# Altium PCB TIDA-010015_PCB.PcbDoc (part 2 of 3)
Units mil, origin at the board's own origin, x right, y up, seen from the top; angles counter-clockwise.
Board outline 6299.21 x 3149.61 mil, 2 copper layers (Top Layer, Bottom Layer), stack 64.6 mil thick; 232 components, 110 nets, 524 pads, 83 vias.
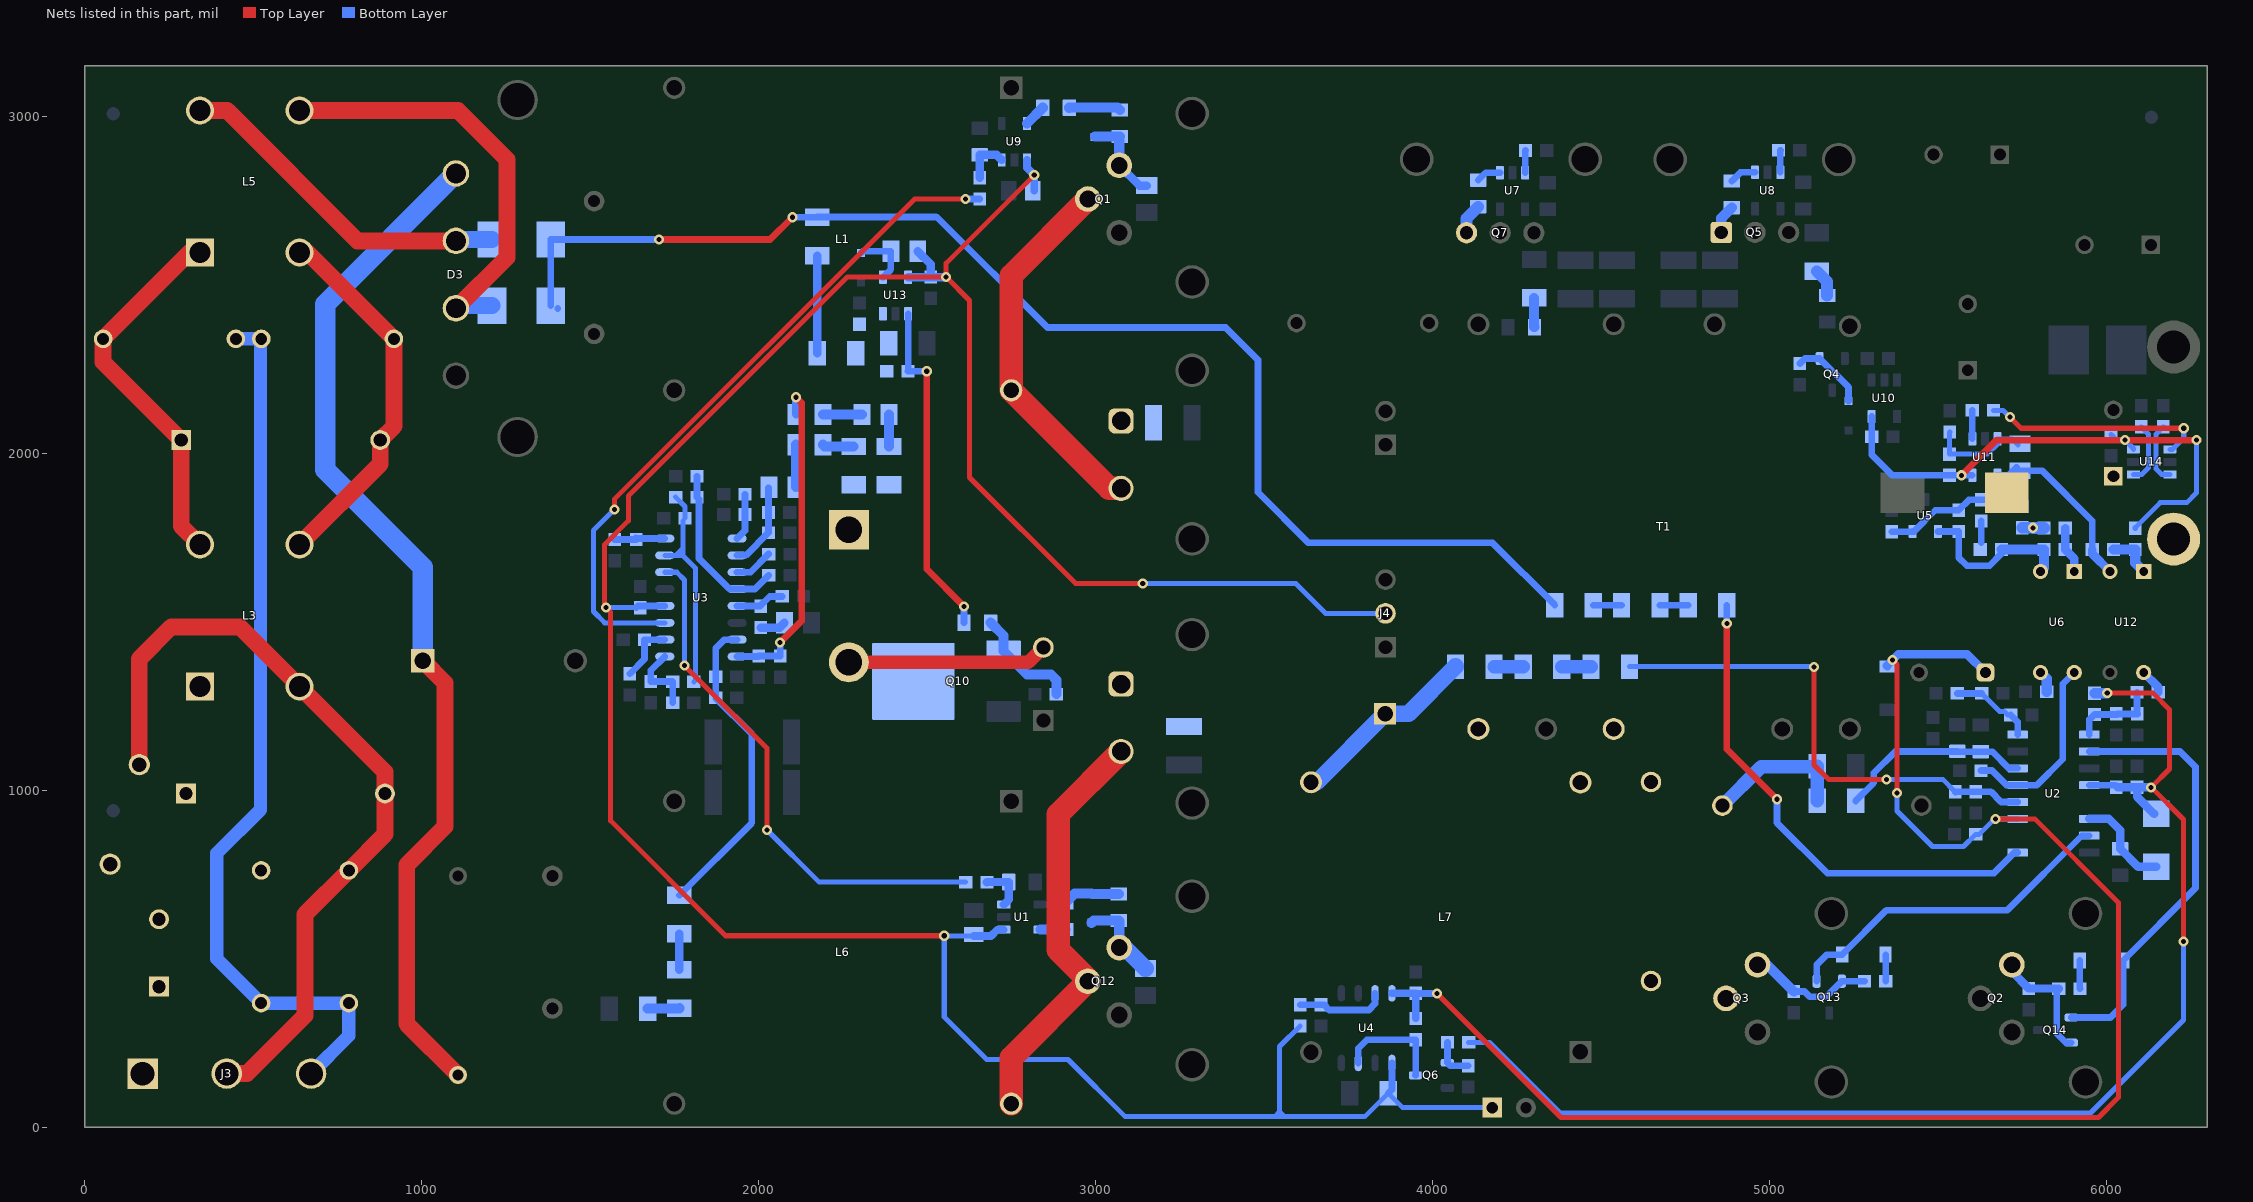
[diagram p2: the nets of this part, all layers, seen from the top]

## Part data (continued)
C34: "CAP, CERM, 820 pF, 50 V, +/- 5%, C0G/NP0, 0603", Cap_Case=0603, Manufacturer=AVX, Supplier Part Number 1=478-1186-1-ND, TempCo=C0G/NP0, Tolerance_%=5, Value1="0.052 ohm", Value2=50V, ValueDisplayed=820pF
C35: library part CMP-0007347-5, "CAP, CERM, 4.7 uF, 25 V, +/- 10%, X5R, 0603", Cap_Case=0603, Manufacturer=MuRata, Supplier Part Number 1=490-7203-1-ND, TempCo=X5R, Tolerance_%=10%, Value1=Unknown, Value2=25V, ValueDisplayed=4.7uF
C36: "CAP, CERM, 2.2 µF, 16 V, +/- 10%, X5R, 0805", Cap_Case=0805, Manufacturer=AVX, Supplier Part Number 1=478-2580-1-ND, TempCo=X5R, Tolerance_%=10, Value1="0.009 ohm", Value2=16V, ValueDisplayed=2.2µF
C38: library part CMP-0007445-4, "CAP, CERM, 0.22 uF, 50 V, +/- 10%, X7R, 0603", Cap_Case=0603, Manufacturer=MuRata, Supplier Part Number 1=490-12546-1-ND, TempCo=X7R, Tolerance_%=10%, Value1=Unknown, Value2=50V, ValueDisplayed=0.22uF
C39: "CAP, CERM, 150 pF, 1000 V, +/- 5%, U2J, 1206", Cap_Case=1206, Manufacturer=MuRata, Supplier Part Number 1=490-4302-1-ND, TempCo=U2J, Tolerance_%=5, Value1=Unknown, Value2=1000V, ValueDisplayed=150pF
C40: library part GRM31A7U3A151JW31D, "CAP CER 82PF 1KV U2J 1206", Cap_Case=1206, Manufacturer=MuRata, Supplier Part Number 1=490-8332-1-ND, TempCo=U2J, Tolerance_%=5, Value1=Unknown, Value2=1000V, ValueDisplayed=82pF
C41: "CAP, CERM, 1000 pF, 100 V, +/- 20%, X7R, 0603", Cap_Case=0603, Manufacturer=AVX, Supplier Part Number 1=478-3699-1-ND, TempCo=X7R, Tolerance_%=20, Value1="0.276 ohm", Value2=100V, ValueDisplayed=1000pF
C42: library part CMP-0006757-5, "CAP, CERM, 0.047 uF, 25 V, +/- 5%, X7R, 0603", Cap_Case=0603, Manufacturer=AVX, Supplier Part Number 1=478-3716-1-ND, TempCo=X7R, Tolerance_%=5%, Value1="0.052 ohm", Value2=25V, ValueDisplayed=0.047uF
C43: "CAP, CERM, 680 pF, 50 V, +/- 10%, X7R, 0603", Cap_Case=0603, Manufacturer=MuRata, Supplier Part Number 1=490-1491-1-ND, TempCo=X7R, Tolerance_%=10, Value1=Unknown, Value2=50V, ValueDisplayed=680pF
C44 C45: library part CMP-0008475-2, "CAP, CERM, 330 pF, 100 V, +/- 5%, C0G/NP0, 1206", Cap_Case=1206, Manufacturer=AVX, Supplier Part Number 1=478-1447-1-ND, TempCo=C0G/NP0, Tolerance_%=5%, Value1="0.392 ohm", Value2=100V, ValueDisplayed=330pF
C46 C48: "CAP, CERM, 1 µF, 25 V, +/- 10%, X7R, 0805", Cap_Case=0805, Manufacturer=Kemet, Supplier Part Number 1=399-8004-1-ND, TempCo=X7R, Tolerance_%=10, Value1=Unknown, Value2=25V, ValueDisplayed=1µF
C50: "CAP, CERM, 10 pF, 50 V,+/- 5%, C0G/NP0, 0603", Cap_Case=0603, Manufacturer=AVX, Supplier Part Number 1=478-1163-1-ND, TempCo=C0G/NP0, Tolerance_%=5, Value1="0.403 ohm", Value2=50V, ValueDisplayed=10pF
C51: "CAP, CERM, 1uF, 25V, +/-10%, X5R, 1206", Cap_Case=1206, Manufacturer=MuRata, Supplier Part Number 1=490-1807-1-ND, TempCo=X5R, Tolerance_%=10, Value1="0.01 ohm", Value2=25V, ValueDisplayed=1uF
C53 C54: library part CMP-0007356-5, "CAP, CERM, 2.2 uF, 35 V, +/- 10%, X5R, 0603", Cap_Case=0603, Manufacturer=MuRata, Supplier Part Number 1=490-7204-6-ND, TempCo=X5R, Tolerance_%=10%, Value1=Unknown, Value2=35V, ValueDisplayed=2.2uF
C55 C57: library part CMP-0007006-5, "CAP, CERM, 1 uF, 25 V, +/- 10%, X5R, 0603", Cap_Case=0603, Manufacturer=TDK, Supplier Part Number 1=445-5146-1-ND, TempCo=X5R, Tolerance_%=10%, Value1=Unknown, Value2=25V, ValueDisplayed=1uF
C56: library part CMP-0081052-1, "CAP, CERM, 4.7 µF, 16 V,+/- 10%, X5R, AEC-Q200 Grade 3, 0603", Cap_Case=0603, Manufacturer=MuRata, Supplier Part Number 1=490-12319-1-ND, TempCo=X5R, Tolerance_%=10%, Value2=16V, ValueDisplayed=4.7µF
C58 C59: "CAP, CERM, 100 pF, 50 V,+/- 5%, C0G/NP0, 0805", Cap_Case=0805, Manufacturer=AVX, Supplier Part Number 1=478-1316-1-ND, TempCo=C0G/NP0, Tolerance_%=5, Value1="0.356 ohm", Value2=50V, ValueDisplayed=100pF
C60: library part CMP-0064896-2, "1000µF 35V Aluminum Electrolytic Capacitors Radial, Can 10000 Hrs @ 105°C", Cap_Case=10x12.5, Manufacturer=Panasonic, Supplier Part Number 1=P10323-ND, Tolerance_%=20%, Value2=35V, ValueDisplayed=1000µF
C67 C68 C72 C73: "CAP, CERM, 4.7 µF, 100 V, +/- 10%, X7S, 1210", Cap_Case=1210, Manufacturer=TDK, Supplier Part Number 1=445-8912-1-ND, TempCo=X7S, Tolerance_%=10, Value1=Unknown, Value2=100V, ValueDisplayed=4.7µF
D1 D5: library part CMP-0029037-1, "Diode, Ultrafast, 600 V, 8 A, TH", Manufacturer="ON Semiconductor", Supplier Part Number 1=MUR860GOS-ND, Value1=8A, Value2=0.98V
D2 D6: "Diode, Schottky, 30V, 0.2A, SOD-323", Manufacturer="ON Semiconductor", Supplier Part Number 1=BAT54HT1OSCT-ND, Value1=0.2A, Value2=30V
D3: library part GBU4A-BP, "RECT BRIDGE GPP 1000V 25A GBU", Manufacturer="Comchip Technology", Value1=8A, Value2=50V
D4: library part CMP-0005844-2, "Diode, Zener, 15 V, 300 mW, SOD-323", Manufacturer="NXP Semiconductor", Power_W=300mW, Supplier Part Number 1=568-6280-1-ND, Value1=0.3W
D7 D8 D11: "Diode, Schottky, 30 V, 0.35 A, SOD-123", Manufacturer="Diodes Inc.", Supplier Part Number 1=SD103-BWDICT-ND, Value1=0.35A, Value2=0.55V
D9 D10: "Diode, P-N, 1000 V, 1 A, SMB", Manufacturer="Diodes Inc.", Supplier Part Number 1=RS1MB-FDICT-ND, Value1=1A, Value2=1.3V
D18: "Diode, Ultrafast, 600 V, 1 A, SMA", Manufacturer="Diodes Inc.", Supplier Part Number 1=US1J-FDICT-ND, Value1=1A, Value2=1.7V
D20: library part CMP-0005865-1, "Diode, Zener, 5.1 V, 200 mW, SOD-323", Manufacturer="Diodes Inc.", Power_W=200mW, Supplier Part Number 1=BZT52C5V1S-FDICT-ND, Value1=0.2W
F1: "FUSE, BOARD MOUNT, 10 A, 300 V, TH-2P", Manufacturer="LITTELFUSE INC"
FID1 FID2 FID3: "Fiducial mark.  There is nothing to buy or mount.", Manufacturer=N/A
H1 H2 H3 H4 H5 H6: "Bumpon, Hemisphere, 0.44 X 0.20, Clear", Manufacturer=3M, Supplier Part Number 1=SJ5303-7-ND
H7: library part CMP-0004065-1, "HEATSINK, ALUM, ANOD, for TO-220", Manufacturer="Assman WSW", Supplier Part Number 1=AE10901-ND
J1: library part CMP-0054792-1, "Header, 2.54 mm, 1x1, Gold, TH", Manufacturer="Wurth Elektronik", Supplier Part Number 1=732-5314-ND
J2: library part CMP-0055085-1, "Header, 100mil, 2x1, TH", Manufacturer=Mill-Max, Supplier Part Number 1=ED7202-ND
J3: "Header(Shrouded), 6.35mm, 3x1, Tin, TH", Manufacturer="TE Connectivity", Supplier Part Number 1=A1468-ND
J4: library part CMP-0055332-1, "Header, 2.54mm, 3x1, Tin, TH", Color=Black, Current_A=4A, Manufacturer=Molex, Supplier Part Number 1=WM50016-03-ND, Voltage_V=250V
J5: library part CMP-0055333-1, "Header, 2.54mm, 2x1, Tin, TH", Color=Black, Current_A=4A, Manufacturer=Molex, Supplier Part Number 1=WM50016-02-ND, Voltage_V=250V
L1 L6: library part PFC4124QM-161K06D-00, "Transformer, 160 uH, TH"
L2: library part 7447020, "Inductor, Toroid, Powdered Iron, 150 µH, 5A, TH", Manufacturer="Wurth Elektronik", Supplier Part Number 1=732-1427-ND, Value1="0.16 ohm", Value2=5A, ValueDisplayed=150µH
L3 L5: "FILTER, WE-CMBNC COMMON MODE POWER LINE CHOKE, 1mH, 15A, VERTICAL, TH-4P", Manufacturer="Wurth Elektronics"
L4: library part CMP-0062077-1, "Inductor, Ferrite, 300 nH, 32 A, 0.00031 ohm, SMD", Manufacturer="Pulse Engineering", Supplier Part Number 1=553-2161-1-ND, Value1="0.00031 ohm", Value2=32A, ValueDisplayed=300nH
L7: library part 1140-331K-RC, "Inductor, Ferrite, 330 µH, 6.1 A, 0.074 ohm, TH"
Logo1: library part Pb-Free
Logo2: library part ESD_Susceptible, "ESD Susceptible Symbol"
LOGO3 LOGO9: library part IEC_HotSurface, "IEC 61010-1 Hot Surface Warning"
LOGO4 LOGO7 LOGO8 LOGO10: library part IEC_HighVoltage, "IEC 61010-1 High Voltage Warning"
Logo6: library part FCC_disclaimer, "FCC_disclaimer"
M1 M2 M3 M4 M5 M6 M7 M8: "HEATSINK, ALUMINIUM WITH CLIP, VERTICAL MOUNT, SOLDERABLE PIN, TO-220", Manufacturer=OHMITE
Q1 Q2 Q3 Q12: library part CMP-0001223-3, "MOSFET N-CHANNEL 600V 26A TO220", Alternate Manufacturer=None, Manufacturer="Infineon Technologies", PartNumber=IPA60R120P7XKSA1, Supplier Part Number 1=IPA60R120P7XKSA1-ND, Value2="37 nC"
Q4: library part CMP-0000488-2, "Transistor, NPN, 60 V, 0.5 A, AEC-Q101, SOT-23", Manufacturer="ON Semiconductor", Supplier Part Number 1=MMBTA05LT1GOSCT-ND, Value1="0.5 A"
Q5 Q7: library part CMP-0000914-1, "MOSFET, N-CH, 80 V, 100 A, KCS0003B (TO-220-3)", Alternate Manufacturer=None, Manufacturer="Texas Instruments", Supplier Part Number 1=296-37286-5-ND, Value2="38 nC"
Q6: library part CMP-0000421-2, "Transistor, NPN, 30 V, 0.6 A, SOT-23", Manufacturer="ON Semiconductor", Supplier Part Number 1=MMBT2222LT1GOSCT-ND, Value1="0.6 A", Value2=300
Q10: library part CMP-0001138-3, "MOSFET, N-CH, 600 V, 4 A, DPAK", Alternate Manufacturer=None, Manufacturer=AOS, Supplier Part Number 1=785-1265-1-ND, Value2="6 nC"
Q13 Q14: library part "BC858C-7-F, Diodes Inc.", "Transistor, PNP, 30 V, 0.1 A, SOT-23", Manufacturer="Diodes Inc.", Supplier Part Number 1=BC858C-7-F-ND, Value1="0.1 A", Value2=600
R1 R2 R55 R64 R72: "RES, 10 k, 0.01%, 0.063 W, 0603", Manufacturer="Stackpole Electronics Inc", Power_W=0.063, Supplier Part Number 1=RNCF0603TKY10K0CT-ND, TempCo="5 ppm/C", Tolerance_%=0.01, Value1=0.01%, Value2=0.063W, Value_Code=10k0, ValueDisplayed=10k
R3: library part CMP-0018911-2, "RES, 200, 0.1%, 0.125 W, 0805", Manufacturer="Susumu Co Ltd", Power_W=125mW, Supplier Part Number 1=RG20P200BCT-ND, TempCo="25 ppm/C", Tolerance_%=0.1%, Value2=0.125W, Value_Code=200R, ValueDisplayed=200
R4 R5 R18: "RES, 18.2, 1%, 0.125 W, 0805", Manufacturer=Vishay-Dale, Power_W=0.125, Supplier Part Number 1=541-18.2CCT-ND, TempCo="100 ppm/C", Tolerance_%=1, Value1=1%, Value2=0.125W, Value_Code=18R2, ValueDisplayed=18.2
R6 R19 R74: "RES, 10.0 k, 1%, 0.125 W, 0805", Manufacturer=Vishay-Dale, Power_W=0.125, Supplier Part Number 1=541-10.0KCCT-ND, TempCo="100 ppm/C", Tolerance_%=1, Value1=1%, Value2=0.125W, Value_Code=10k0, ValueDisplayed=10.0k
R7 R8: "RES, 0.03, 1%, 2 W, 2512", Manufacturer="Stackpole Electronics Inc", Power_W=2, Supplier Part Number 1=CSRN2512FK30L0CT-ND, TempCo="200 ppm/C", Tolerance_%=1, Value1=1%, Value2=2W, Value_Code=R030, ValueDisplayed=0.03
R9: library part CMP-0024361-3, "RES, 59.7 k, 0.1%, 0.1 W, 0603", Manufacturer="Yageo America", Power_W=100mW, TempCo="25 ppm/C", Tolerance_%=0.1%, Value2=0.1W, Value_Code=59k7, ValueDisplayed=59.7k
R10 R22 R31: "RES, 1.00 k, 1%, 0.25 W, 1206", Manufacturer=Vishay-Dale, Power_W=0.25, Supplier Part Number 1=541-1.00KFCT-ND, TempCo="100 ppm/C", Tolerance_%=1, Value1=1%, Value2=0.25W, Value_Code=1k00, ValueDisplayed=1.00k
R11 R37 R39 R41: "RES, 66.5 k, 1%, 0.1 W, 0603", Manufacturer=Vishay-Dale, Power_W=0.1, Supplier Part Number 1=541-66.5KHCT-ND, TempCo="100 ppm/C", Tolerance_%=1, Value1=1%, Value2=0.1W, Value_Code=66k5, ValueDisplayed=66.5k
R12 R49: "RES, 10.0 k, 1%, 0.1 W, 0603", Manufacturer=Vishay-Dale, Power_W=0.1, Supplier Part Number 1=541-10.0KHCT-ND, TempCo="100 ppm/C", Tolerance_%=1, Value1=1%, Value2=0.1W, Value_Code=10k0, ValueDisplayed=10.0k
R14: library part CMP-0022705-3, "RES, 49.9 k, 1%, 0.1 W, AEC-Q200 Grade 0, 0603", Manufacturer=Panasonic, Power_W=100mW, Supplier Part Number 1=P49.9KHCT-ND, TempCo="100 ppm/C", Tolerance_%=1%, Value2=0.1W, Value_Code=49k9, ValueDisplayed=49.9k
R15 R16: "RES, 2.2, 5%, 0.125 W, 0805", Manufacturer=Vishay-Dale, Power_W=0.125, Supplier Part Number 1=541-2.2ACT-ND, TempCo="200 ppm/C", Tolerance_%=5, Value1=5%, Value2=0.125W, Value_Code=2R20, ValueDisplayed=2.2
R17 R47 R71 R73: "RES, 6.04 k, 1%, 0.1 W, 0603", Manufacturer=Vishay-Dale, Power_W=0.1, Supplier Part Number 1=541-6.04KHCT-ND, TempCo="100 ppm/C", Tolerance_%=1, Value1=1%, Value2=0.1W, Value_Code=6k04, ValueDisplayed=6.04k
R20: library part CMP-0018672-3, "RES, 3.0 M, 5%, 0.25 W, AEC-Q200 Grade 0, 1206", Manufacturer=Vishay-Dale, Power_W=250mW, Supplier Part Number 1=541-3.0MECT-ND, TempCo="200 ppm/C", Tolerance_%=5%, Value2=0.25W, Value_Code=3M00, ValueDisplayed=3.0M
R21 R23 R33 R87: library part CMP-0018647-3, "RES, 2.7 M, 5%, 0.25 W, AEC-Q200 Grade 0, 1206", Manufacturer=Vishay-Dale, Power_W=250mW, Supplier Part Number 1=541-2.7MECT-ND, TempCo="200 ppm/C", Tolerance_%=5%, Value2=0.25W, Value_Code=2M70, ValueDisplayed=2.7M
R24 R26: "RES, 16.5 k, 1%, 0.1 W, 0603", Manufacturer=Vishay-Dale, Power_W=0.1, Supplier Part Number 1=541-16.5KHCT-ND, TempCo="100 ppm/C", Tolerance_%=1, Value1=1%, Value2=0.1W, Value_Code=16k5, ValueDisplayed=16.5k
R25: "RES, 750 k, 1%, 0.1 W, 0603", Manufacturer=Vishay-Dale, Power_W=0.1, Supplier Part Number 1=541-750KHCT-ND, TempCo="100 ppm/C", Tolerance_%=1, Value1=1%, Value2=0.1W, Value_Code=750k
R27 R34 R46 R86: "RES, 2.74 M, 1%, 0.125 W, 0805", Manufacturer=Vishay-Dale, Power_W=0.125, Supplier Part Number 1=541-2.74MCCT-ND, TempCo="100 ppm/C", Tolerance_%=1, Value1=1%, Value2=0.125W, Value_Code=2M74, ValueDisplayed=2.74M
R28 R77: "RES, 511k ohm, 1%, 0.25W, 1206", Manufacturer=Vishay-Dale, Power_W=0.25, Supplier Part Number 1=541-511KFCT-ND, TempCo="100 ppm/C", Tolerance_%=1, Value1=1%, Value2=0.25W, Value_Code=511k
R29 R36: "RES, 330 k, 5%, 0.25 W, 1206", Manufacturer=Vishay-Dale, Power_W=0.25, Supplier Part Number 1=541-330KECT-ND, TempCo="200 ppm/C", Tolerance_%=5, Value1=5%, Value2=0.25W, Value_Code=330k
R30: "RES, 100, 1%, 0.1 W, 0603", Manufacturer=Vishay-Dale, Power_W=0.1, Supplier Part Number 1=541-100HCT-ND, TempCo="100 ppm/C", Tolerance_%=1, Value1=1%, Value2=0.1W, Value_Code=100R, ValueDisplayed=100
R32 R70: "RES, 487 k, 1%, 0.1 W, 0603", Manufacturer=Vishay-Dale, Power_W=0.1, Supplier Part Number 1=541-487KHCT-ND, TempCo="100 ppm/C", Tolerance_%=1, Value1=1%, Value2=0.1W, Value_Code=487k
R35: "RES, 133 k, 1%, 0.1 W, 0603", Manufacturer=Vishay-Dale, Power_W=0.1, Supplier Part Number 1=541-133KHCT-ND, TempCo="100 ppm/C", Tolerance_%=1, Value1=1%, Value2=0.1W, Value_Code=133k
R38 R40: "RES, 22, 5%, 0.1 W, 0603", Manufacturer=Vishay-Dale, Power_W=0.1, Supplier Part Number 1=541-22GCT-ND, TempCo="200 ppm/C", Tolerance_%=5, Value1=5%, Value2=0.1W, Value_Code=22R0, ValueDisplayed=22
R42: "RES, 7.50 k, 1%, 0.1 W, 0603", Manufacturer=Vishay-Dale, Power_W=0.1, Supplier Part Number 1=541-7.50KHCT-ND, TempCo="100 ppm/C", Tolerance_%=1, Value1=1%, Value2=0.1W, Value_Code=7k50, ValueDisplayed=7.50k
R43: "RES, 374 k, 1%, 0.25 W, 1206", Manufacturer=Vishay-Dale, Power_W=0.25, Supplier Part Number 1=541-374KFCT-ND, TempCo="100 ppm/C", Tolerance_%=1, Value1=1%, Value2=0.25W, Value_Code=374k
R44 R45: "RES, 4.7 k, 5%, 0.1 W, 0603", Manufacturer=Bourns, Power_W=0.1, Supplier Part Number 1=CR0603-JW-472GLFCT-ND, TempCo="200 ppm/C", Tolerance_%=5, Value1=5%, Value2=0.1W, Value_Code=4k70, ValueDisplayed=4.7k
R48: "RES, 147 k, 1%, 0.1 W, 0603", Manufacturer=Vishay-Dale, Power_W=0.1, Supplier Part Number 1=541-147KHCT-ND, TempCo="100 ppm/C", Tolerance_%=1, Value1=1%, Value2=0.1W, Value_Code=147k
R50: "RES, 16.9 k, 1%, 0.1 W, 0603", Manufacturer=Vishay-Dale, Power_W=0.1, Supplier Part Number 1=541-16.9KHCT-ND, TempCo="100 ppm/C", Tolerance_%=1, Value1=1%, Value2=0.1W, Value_Code=16k9, ValueDisplayed=16.9k
R51 R63: library part CMP-0022010-4, "RES, 113 k, 1%, 0.1 W, AEC-Q200 Grade 0, 0603", Manufacturer=Vishay-Dale, Power_W=100mW, Supplier Part Number 1=541-113KHCT-ND, TempCo="100 ppm/C", Tolerance_%=1%, Value2=0.1W, Value_Code=113k
R52 R53: "RES, 10, 5%, 0.125 W, 0805", Manufacturer=Vishay-Dale, Power_W=0.125, Supplier Part Number 1=541-10ACT-ND, TempCo="200 ppm/C", Tolerance_%=5, Value1=5%, Value2=0.125W, Value_Code=10R0, ValueDisplayed=10
R56: library part CMP-0023630-3, "RES, 100 k, 0.1%, 0.1 W, 0603", Manufacturer="Yageo America", Power_W=100mW, Supplier Part Number 1=603-RT0603BRD07100KL, TempCo="25 ppm/C", Tolerance_%=0.1%, Value2=0.1W, Value_Code=100k
R58 R59: "RES, 10.0, 1%, 0.25 W, 0603", Manufacturer=Vishay-Dale, Power_W=0.25, Supplier Part Number 1=541-10.0SCT-ND, TempCo="100 ppm/C", Tolerance_%=1, Value1=1%, Value2=0.25W, Value_Code=10R0, ValueDisplayed=10.0
R60 R61: "RES, 4.7, 5%, 0.125 W, 0805", Manufacturer=Vishay-Dale, Power_W=0.125, Supplier Part Number 1=541-4.7ACT-ND, TempCo="200 ppm/C", Tolerance_%=5, Value1=5%, Value2=0.125W, Value_Code=4R70, ValueDisplayed=4.7
R62: library part CMP-0023252-5, "RES, 6.81 k, 1%, 0.1 W, 0603", Manufacturer=Yageo, Power_W=100mW, Supplier Part Number 1=311-6.81KHRCT-ND, TempCo="100 ppm/C", Tolerance_%=1%, Value2=0.1W, Value_Code=6k81, ValueDisplayed=6.81k
R65: library part CMP-0015849-2, "RES, 0.0005, 1%, 2 W, 2512", Manufacturer=Vishay-Dale, Power_W=2W, TempCo="400 ppm/C", Tolerance_%=1%, Value_Code=L5000, ValueDisplayed=0.0005
R66 R78: library part CMP-0022004-4, "RES, 10.0, 1%, 0.25 W, AEC-Q200 Grade 0, 0603", Manufacturer=Vishay-Dale, Power_W=250mW, Supplier Part Number 1=541-10.0SCT-ND, TempCo="100 ppm/C", Tolerance_%=1%, Value2=0.25W, Value_Code=10R0, ValueDisplayed=10.0
R67: library part CMP-0020980-3, "RES, 1.00 M, 1%, 0.125 W, AEC-Q200 Grade 0, 0805", Manufacturer=Vishay-Dale, Power_W=125mW, Supplier Part Number 1=541-1.00MCCT-ND, TempCo="100 ppm/C", Tolerance_%=1%, Value2=0.125W, Value_Code=1M00, ValueDisplayed=1.00M
R68: library part CMP-0022731-2, "RES, 1.00 M, 1%, 0.125 W, 0603", Manufacturer=Vishay/Beyschlag, Power_W=125mW, Supplier Part Number 1=MCT0603-1.00M-CFCT-ND, TempCo="50 ppm/C", Tolerance_%=1%, Value2=0.125W, Value_Code=1M00, ValueDisplayed=1.00M
R69: library part CMP-0022697-2, "RES, 330 k, 1%, 0.1 W, AEC-Q200 Grade 0, 0603", Manufacturer=Panasonic, Power_W=100mW, Supplier Part Number 1=P330KHCT-ND, TempCo="100 ppm/C", Tolerance_%=1%, Value2=0.1W, Value_Code=330k
R75: library part CMP-0022142-4, "RES, 1.10 M, 1%, 0.1 W, AEC-Q200 Grade 0, 0603", Manufacturer=Vishay-Dale, Power_W=100mW, Supplier Part Number 1=541-1.10MHCT-ND, TempCo="100 ppm/C", Tolerance_%=1%, Value2=0.1W, Value_Code=1M10, ValueDisplayed=1.10M
R76: "RES, 49.9k ohm, 1%, 0.25W, 1206", Manufacturer=Vishay-Dale, Power_W=0.25, Supplier Part Number 1=541-49.9KFCT-ND, TempCo="100 ppm/C", Tolerance_%=1, Value1=1%, Value2=0.25W, Value_Code=49k9
R88: library part CMP-0022686-2, "RES, 124 k, 1%, 0.1 W, AEC-Q200 Grade 0, 0603", Manufacturer=Panasonic, Power_W=100mW, Supplier Part Number 1=P124KHCT-ND, TempCo="100 ppm/C", Tolerance_%=1%, Value2=0.1W, Value_Code=124k
R89: library part CMP-0022659-4, "RES, 95.3 k, 1%, 0.1 W, AEC-Q200 Grade 0, 0603", Manufacturer=Vishay-Dale, Power_W=100mW, Supplier Part Number 1=541-95.3KHCT-ND, TempCo="100 ppm/C", Tolerance_%=1%, Value2=0.1W, Value_Code=95k3, ValueDisplayed=95.3k
R90: "RES, 82.5 k, 1%, 0.1 W, 0603", Manufacturer=Vishay-Dale, Power_W=0.1, Supplier Part Number 1=541-82.5KHCT-ND, TempCo="100 ppm/C", Tolerance_%=1, Value1=1%, Value2=0.1W, Value_Code=82k5, ValueDisplayed=82.5k
RF1: "RES, 47, 10%, 2 W, Fusible, TH", Manufacturer="TT Electronics/IRC", Power_W=2, Supplier Part Number 1=985-1022-1-ND, TempCo="100 ppm/C", Tolerance_%=10, Value1=10%, Value2=2W, Value_Code=47R0, ValueDisplayed=47
RV1: "Varistor 275V RMS 10MM Radial, TH", Manufacturer="EPCOS Inc", Supplier Part Number 1=495-1433-ND
T1: "Transformer, TH", Manufacturer=Payton
U1 U9: library part CMP-0066947-1, "4A/4A Single Channel High-speed Low-side Gate Driver, DBV0005A (SOT-23-5)", Alternate Manufacturer="Texas Instruments", Alternate PartNumber=UCC27517DBVT
U2: "Enhanced LLC Resonant Controller with Driver, DDB0014A (SOIC-14)", Alternate Manufacturer="Texas Instruments"
U3: library part CMP-0065070-1, "Natural Interleaving Transition Mode PFC Controller with Improved Light Load Efficiency, D0016A (SOIC-16)", Alternate Manufacturer="Texas Instruments", Alternate PartNumber=UCC28064D
U4: library part CMP-0076214-1, "Series of Adjustable Micropower Voltage Regulators, D0008A (SOIC-8)", Alternate Manufacturer="Texas Instruments", Alternate PartNumber=LP2951ACM/NOPB
U5: "Adjustable Precision Shunt Regulator, 34 ppm / degC, 100 mA, 0 to 70 degC, 3-pin SOT-23 (DBZ), Green (RoHS & no Sb/Br)", Alternate Manufacturer="Texas Instruments", Alternate PartNumber=Equivalent, Rating=Catalog, Supplier Part Number 1=296-17328-2-ND, Temp Coeff(Typ)(ppm/ degree C)=34
U6 U12: "Optocoupler, 5.3 kV, 50-600% CTR, TH", Manufacturer=Vishay-Semiconductor, Supplier Part Number 1=VO618A-ND, Voltage_Isolation_Vrms=5300V
U7 U8: "UCC24612-1DBV, DBV0005A (SOT-23-5)", Alternate Manufacturer="Texas Instruments", Alternate PartNumber=UCC24612-1DBVT
U10: library part CMP-0070878-1, "Micropower 100 mA Ultra Low-Dropout Regulator, 5-pin SOT-23, Pb-Free", Manufacturer="Texas Instruments", PackageTopMarking=L05B*XTT, PowerWise=N
U11: library part CMP-0065409-1, "SINGLE DIFFERENTIAL COMPARATOR, DBV0005A (SOT-23-5)", Alternate Manufacturer="Texas Instruments", Alternate PartNumber=TL331IDBVT
U13: library part CMP-0073526-1, "36V, Low-Power, RRO, General-Purpose Operational Amplifier, DBV0005A (SOT-23-5)", Alternate Manufacturer="Texas Instruments", Alternate PartNumber=TLV171IDBVT
U14: library part CMP-0013228-2, "Bidirectional, Low- and High-Side Measurement, Multichannel, Voltage Output, Current-Sense Amplifier, DBV0006A (SOT-6)", Alternate Manufacturer="Texas Instruments"
ZZ1: library part AssemblyNoteLabel, Alternate Manufacturer=-
ZZ2 ZZ3 ZZ4: library part AssemblyNote, Alternate Manufacturer=-

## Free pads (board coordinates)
  round 157.48 hole 98.43: 1(6199,1745) 1(6199,2315)

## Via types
v1: diameter 30, hole 15, Top Layer to Bottom Layer, 83 vias

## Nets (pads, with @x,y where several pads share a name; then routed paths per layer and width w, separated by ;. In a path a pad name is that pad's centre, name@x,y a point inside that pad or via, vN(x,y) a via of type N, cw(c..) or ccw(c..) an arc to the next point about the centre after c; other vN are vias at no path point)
5V: C56.1 C57.1 R68.2 R71.2 U10.5 U11.5 U14.6 | length 1653.5
  Top Layer w20: v1(5569,1934.36) 5673.14,2038.5 v1(6055,2038.5) 6266.5,2038.5 v1(6267,2039) v1@6272.01,2039
  Bottom Layer w15: C57.1@6013,2055.5 6029.99,2038.5 v1(6055,2038.5) 6079.73,2013.77 U14.6@6079.73,2011.4 ; R71.2@6085,1776.99 6085,1779 6159,1853 6237.82,1853 6267,1882.18 v1(6267,2039)
  Bottom Layer w20: U10.5@5303.03,2108.75 5303.03,2048.91 5303.01,1995.99 5364.91,1934.09 R68.2@5533.87,1934.09 5534.15,1934.36 v1(5569,1934.36) U11.5@5601.67,1934.36
12V: C32.1 C35.2 D18.2 R25.2 R63.1 U2.12 | length 3872.8
  Top Layer w15: v1@5993.5,1287.84 6138.16,1287.84 6187,1239 6187,1063 v1(6132.35,1008.35) 6228,912.7 v1(6228,551)
  Bottom Layer w15: R63.1@4107.01,251.65 4169.35,251.65 4379,42 5952,42 6228,318 v1(6228,551) ; R25.2@5964,1287.5 5964.34,1287.84 v1@5993.5,1287.84
  Bottom Layer w20: U2.12@5948.77,1014.85 6026.06,1014.85 C32.1@6032.56,1008.35
  Bottom Layer w25: C32.1@6032.56,1008.35 C35.2@6090.4,1008.35 ; v1(6132.35,1008.35) C35.2@6090.4,1008.35 ; D18.2@6141,929.74 6090.4,980.34 C35.2@6090.4,1008.35
  Bottom Layer w30: R25.2@5964,1287.5 6001.5,1287.5 v1(6002,1288)
24V: C76.1 L4.2 pad.1@6199,1745 R17.2 R48.2 | length 64.5
  Bottom Layer w35: R48.2@5750,1778.53 v1(5782,1778.53) 5782.5,1778.03 R17.2@5814.27,1778.03
390V: C1.1 C2.1 C7.1 C65.1 D1.1 D5.1 J1.1 L7.3 Q3.2 R20.2 R43.2 R87.2 | length 571.1
  Bottom Layer w50: L7.3@3639.39,1023.39 3655.95,1023.39 J1.1@3859.25,1226.69 3928.51,1226.69 R43.2@4068.37,1366.54
AUX_15V: C15.2 C23.1 C27.1 C30.2 C51.1 J2.1 J4.2 R51.2 R74.2 U1.1 U3.12 U4.1 U9.1 U13.5 | length 8898.1
  Top Layer w15: v1(2551,568) 1902,568 1561,909 1561,1528 v1(1547,1542) 1542.48,1546.52 1542.48,1728.48 1613.5,1799.5 1613.5,1872.76 2263.24,2522.5 v1(2556.56,2522.5) ; v1(2818,2825) 2556.56,2563.56 v1(2556.56,2522.5) ; v1(3140,1613) 2941,1613 2626,1928 2626,2453.05 v1(2556.56,2522.5)
  Bottom Layer w15: v1(1547,1542) 1636.21,1542 C30.2@1636.71,1541.5 ; C23.1@2638.66,567.4 2551.6,567.4 v1(2551,568) 2551,327 2677,201 2918,201 3088,31 3531.5,31 ; v1(3140,1613) 3594,1613 3682.34,1524.66 J4.2@3860.25,1524.66 ; R51.2@3607,300.5 3546,239.5 3546,45.5 ; J2.1@4177,58 3911.29,58 C51.1@3868.45,100.84 3798.61,31 3560.5,31 ; 3531.5,31 3560.5,31 ; 3531.5,31 3546,45.5 ; 3546,45.5 3560.5,31
  Bottom Layer w20: C30.2@1636.71,1541.5 1641.91,1546.7 U3.12@1721.71,1546.7 ; C51.1@3868.45,100.84 3879.36,111.75 U4.1@3879.36,190.49
  Bottom Layer w23: C23.1@2638.66,567.4 2689.66,567.4 2708.26,586 U1.1@2727.73,586 ; U9.1@2796.4,2869.87 2796.4,2846.85 2818,2825.26 v1(2818,2825) C15.2@2818,2779
  Bottom Layer w25: U13.5@2443.82,2522.13 2510.05,2522.13 C27.1@2510.42,2522.5 ; R74.2@2472.42,2599 2510.42,2561 C27.1@2510.42,2522.5 ; v1(2556.56,2522.5) C27.1@2510.42,2522.5
BLK: C17.1 R2.2 R29.1 U2.4 | length 1487.1
  Top Layer w15: v1(5132,1365) 5132,1074.93 5174.93,1032 v1@5349,1032
  Bottom Layer w15: R29.1@4584.54,1366.54 5130.46,1366.54 v1(5132,1365) ; v1@5349,1032 5513.97,1032 C17.1@5550.47,995.5
  Bottom Layer w20: C17.1@5551.95,994.01 5553.43,995.5 R2.2@5611.61,995.5 5656.5,995.5 5687.15,964.85 U2.4@5736.17,964.85
  other v1: 5347,1032
BW: C20.1 R9.1 R12.2 U2.8 | length 252.2
  Bottom Layer w15: R12.2@5629.5,1287 5682.5,1234 5696,1234 5707,1223 C20.1@5715.5,1223
  Bottom Layer w20: R9.1@5556.5,1287 R12.2@5629.5,1287 ; C20.1@5715.5,1223 5736.17,1202.33 U2.8@5736.17,1164.85
COMP: C34.1 R42.1 U3.5 | length 146
  Bottom Layer w20: U3.5@1936.28,1546.7 2004.8,1546.7 2033.1,1575 C34.1@2070.5,1575
DRV: R5.2 R75.2 U13.1 | length 1018.6
  Top Layer w20: v1(2499,2243) 2499,1655.75 v1(2609.87,1544.87)
  Bottom Layer w20: U13.1@2443.82,2413.87 2443.82,2243.24 R75.2@2443.5,2242.91 2498.91,2242.91 v1(2499,2243) ; R5.2@2609.87,1497 v1(2609.87,1544.87)
EARTH: C6.2 C11.1 C47.2 C49.1 J3.3 | length 2671.3
  Bottom Layer w40: C47.2@448.85,2339.28 C49.1@524.3,2339.28 522,2336.98 522,942 392.34,812.34 392.34,499.81 C6.2@524,368.15 C11.1@784,368.15 784,271 J3.3@672,159
G1: R61.1 U7.1 | length 73.5
  Bottom Layer w20: R61.1@4135.51,2810.22 4157.4,2832.11 U7.1@4199.91,2832.11
G2: R60.2 U8.1 | length 79.7
  Bottom Layer w20: R60.2@4888,2807.37 4913.99,2833.36 U8.1@4956.99,2833.36
GD1: R58.1 U3.14 | length 1564.9
  Top Layer w15: v1(1780.31,1369.44) 2025,1124.75 v1(2025,882)
  Bottom Layer w15: U3.14@1721.71,1646.7 1757.3,1646.7 1780.31,1623.69 v1(1780.31,1369.44) ; v1(2025,882) 2180,727 R58.1@2614.5,727
GD2: R59.1 U3.11 | length 2037.7
  Top Layer w15: v1(1572,1833) 1572,1863.36 2463.14,2754.5 v1(2614.5,2754.5)
  Bottom Layer w15: v1(1572,1833) 1510,1771 1510,1530 1543.3,1496.7 U3.11@1721.71,1496.7
  Bottom Layer w20: v1(2614.5,2754.5) R59.1@2656,2754.5
HO: D7.2 Q13.1 U2.15 | length 1015.9
  Bottom Layer w20: Q13.1@5139.6,433.24 5139.6,480.91 5170.69,512 D7.2@5215.53,512 5347.53,644 5705.47,644 5926.31,864.85 U2.15@5948.77,864.85
I_OUT: R69.1 U14.1 | length 670.3
  Top Layer w15: v1(5713,2107) 5746,2074 v1(6229,2074)
  Bottom Layer w15: R69.1@5664.5,2126.87 5693.13,2126.87 v1(5713,2107) ; U14.1@6188,2011.4 6195.4,2011.4 6229,2045 v1(6229,2074)
ISNS: C19.1 C39.2 R3.2 U2.6 | length 579.7
  Bottom Layer w20: C39.2@5255.37,968 5309.06,1021.69 5309.06,1051.06 5373.09,1115.09 C19.1@5557.41,1115.09 5558.13,1114.36 5660.64,1114.36 5710.15,1064.85 U2.6@5736.17,1064.85
LDO_IN: C16.1 C52.1 C60.1 D11.1 R56.2 U2.3 U4.8 | length 4673.8
  Top Layer w15: v1(4013.01,396.75) 4380.76,29 5975.8,29 6035,88.2 6035,666.64 5786.79,914.85 v1(5670.15,914.85) ; v1(5364.77,1386.23) 5378,1373 v1(5378,992)
  Bottom Layer w15: v1(5378,992) 5378,938.27 5483.27,833 5575.5,833 C16.1@5611.5,869 5622,869 5667.85,914.85 v1(5670.15,914.85) U2.3@5736.17,914.85
  Bottom Layer w22: U4.8@3879.36,397.18 C52.1@3949.49,397.18 C52.1@3949.92,396.75 ; R56.2@3949.92,322.33 C52.1@3949.92,396.75 ; v1(4013.01,396.75) C52.1@3949.92,396.75
  Bottom Layer w25: D11.1@5350,1367.47 5348,1369.47 v1(5364.77,1386.23) 5381.53,1403 5586.43,1403 C60.1@5640.43,1349
LL/SS: C31.1 R25.1 R32.2 R70.2 U2.9 | length 258.9
  Bottom Layer w20: U2.9@5948.77,1164.85 5948.77,1209.61 R25.1@5964,1224.85 ; R25.1@5964,1224.5 R25.1@5964,1224.85 ; C31.1@6090.47,1226.84 R70.2@6090.5,1290 ; C31.1@6092.47,1226.34 6032.56,1226.34 6031.06,1224.85 R25.1@5964,1224.85
LO: D8.2 Q14.1 U2.10 | length 1298.5
  Bottom Layer w20: Q14.1@5895.24,325.4 6011.4,325.4 6049.47,363.47 D8.2@6049.47,495 6263.86,709.39 6263.86,1069.14 6218.15,1114.85 U2.10@5948.77,1114.85
NETA: D9.1 D10.1 R28.1 R31.1 | length 3910.8
  Top Layer w20: v1(1705,2634) 2034.25,2634 v1(2100.34,2700.09)
  Bottom Layer w20: D10.1@1383.01,2438 D9.1@1383.01,2634 v1(1705,2634) ; v1(2100.34,2700.09) R28.1@2174,2700.09 2174,2700.5 2526.41,2700.5 2526.83,2700.09 2529.91,2700.09 2857,2373 3386,2373 3482,2277 3482,1884 3632,1734 4177.83,1734 R31.1@4362.83,1549
NetC1_2: C1.2 Q10.4 RF1.2 | length 595.3
  Top Layer w40: C1.2@2268,1379.15 2800.88,1379.15 RF1.2@2845,1423.27
NetC2_2: C2.2 C3.1 C39.1 C40.1 T1.3 | length 432.9
  Bottom Layer w40: C3.1@4859.72,954 4974.67,1068.95 5139.15,1068.95 C40.1@5141.2,1071 C39.1@5141.2,968
NetC4_1: C4.1 D3.1 L2.1 | length 3093.6
  Top Layer w50: L2.1@1003.62,1384 1070,1317.62 1070,892.29 956,778.29 956,306.72 C4.1@1108,154.72
  Bottom Layer w60: L2.1@1003.62,1384 1003.62,1661.38 714,1951 714,2442 D3.1@1102,2830
NetC6_1: C6.1 C9.1 F1.2 L3.1 RV1.2
NetC9_2: C9.2 C11.2 J3.2 L3.2 RV1.1 | length 2384.3
  Top Layer w50: RV1.1@162.31,1075.64 162.31,1389.31 257,1484 461.01,1484 L3.2@637.64,1307.37 891.28,1053.73 C9.2@891.28,990 891.28,869.13 C11.2@784,761.85 654,631.85 654,331 482,159 J3.2@422,159
NetC10_1: C10.1 C47.1 L3.4 L5.1 | length 1122.9
  Top Layer w50: L3.4@342.36,1728.63 286.72,1784.27 C10.1@286.72,2039 55.15,2270.57 C47.1@55.15,2339.28 311.24,2595.37 L5.1@342.36,2595.37
NetC10_2: C10.2 C49.2 L3.3 L5.2 | length 1113.2
  Top Layer w50: L3.3@637.64,1728.63 877.28,1968.27 C10.2@877.28,2039 918,2079.72 C49.2@918,2339.28 661.91,2595.37 L5.2@637.64,2595.37
NetC18_1: C18.1 U2.5 U6.4 | length 563.6
  Bottom Layer w20: C18.1@5627.5,1058 5660,1058 5703.15,1014.85 U2.5@5736.17,1014.85 5793.14,1014.85 5870,1091.71 5870,1315 U6.4@5904,1349
NetC21_1: C21.1 R39.1 R41.1 U3.4 | length 507.7
  Bottom Layer w20: R41.1@1816.99,1931.5 R39.1@1816.99,1869.5 1823.5,1863 1823.5,1687.5 1914.3,1596.7 U3.4@1936.28,1596.7 1989.2,1596.7 C21.1@2030,1637.5
NetC24_1: C24.1 R24.2 U3.16 | length 150.9
  Bottom Layer w20: R24.2@1572.68,1743.77 C24.1@1636.79,1743.77 ; C24.1@1635.49,1748 1636.79,1746.7 U3.16@1721.71,1746.7
NetC25_1: C25.1 R26.1 U3.1 | length 140.9
  Bottom Layer w20: U3.1@1936.28,1746.7 1959.49,1769.91 C25.1@1959.49,1818 R26.1@1959.49,1878
NetC26_1: C26.1 D18.1 U2.14 | length 290.6
  Bottom Layer w25: U2.14@5948.77,914.85 6006.63,914.85 6040,881.47 C26.1@6040,826.37 6094.11,772.26 D18.1@6148,772.26
NetC28_1: C28.1 R75.1 R76.2 R77.2 U13.3
NetC29_1: C29.1 R30.2 U3.10 | length 179.2
  Bottom Layer w20: R30.2@1618,1345.5 1661.5,1388.99 1661.5,1393.25 1661.7,1393.46 1661.7,1420.54 1661.5,1420.75 C29.1@1661.5,1446 1662.2,1446.7 U3.10@1721.71,1446.7
NetC33_1: C33.1 R34.1 R35.2 U3.2 | length 254.6
  Bottom Layer w20: U3.2@1936.28,1696.7 1962.11,1696.7 C33.1@2029.44,1764.04 R35.2@2029.44,1824.04 R34.1@2029.44,1897.54
NetC36_1: C36.1 R42.2 | length 76.9
  Bottom Layer w25: R42.2@2006,1482.5 2062.8,1482.5 C36.1@2077,1496.7
NetC37_1: C37.1 R11.1 R37.2 U3.9 | length 218.9
  Bottom Layer w20: U3.9@1721.71,1396.7 1679.99,1354.98 C37.1@1679.99,1322.5 1743.96,1322.5 R37.2@1745,1321.46 R11.1@1745,1259.5
NetC38_1: C38.1 R37.1 R39.2 U3.15 | length 665.5
  Bottom Layer w15: U3.15@1721.71,1696.7 1754.69,1696.7 ; R39.2@1754,1869.5 1781.5,1842.01 C38.1@1781.5,1807 ; C38.1@1775.5,1798.01 1775.5,1717.5 ; R37.1@1807.99,1321.46 1812.5,1325.97 1812.5,1658.5 1775.5,1695.5 ; 1754.69,1696.7 1774.3,1696.7 ; 1754.69,1696.7 1765.09,1707.1 ; 1765.09,1707.1 1775.5,1717.5 ; 1765.09,1707.1 1765.09,1705.91 1774.3,1696.7 ; 1774.3,1696.7 1775.5,1695.5 ; 1775.5,1695.5 1775.5,1717.5
NetC41_1: C41.1 R33.2 R88.1 U3.7 | length 940.6
  Bottom Layer w20: R33.2@1765,688.09 1980,903.09 1980,1166.09 1872.52,1273.57 C41.1@1872.52,1274 R88.1@1872.52,1336 1872.52,1420.52 1898.7,1446.7 U3.7@1936.28,1446.7
NetC42_1: C42.1 R49.1 | length 63.3
  Bottom Layer w20: 5628.16,1735.21 R49.1@5628.16,1798.5
NetC42_2: C42.2 C50.2 R47.1 U5.1 U6.2 | length 486.5
  Bottom Layer w20: U5.1@5499.4,1767.76 5499.65,1767.5 C50.2@5561,1767.5 5561,1690.5 5585.5,1666 5652.64,1666 C42.2@5688.44,1701.8
  Bottom Layer w30: C42.2@5688.44,1714 R47.1@5814.45,1714.03 5814.45,1659.45 U6.2@5804,1649
NetC43_1: C43.1 R46.1 R90.2 U3.8 | length 980.6
  Top Layer w20: v1(2064,1438) 2127.76,1501.76 2127.76,2149.24 v1(2111,2166)
  Bottom Layer w20: U3.8@1936.28,1396.7 1999.2,1396.7 C43.1@2000.5,1398 R90.2@2064,1397.99 v1(2064,1438)
  Bottom Layer w25: R46.1@2111,2115 v1(2111,2166)
NetC44_2: C44.2 R52.2 | length 84.7
  Bottom Layer w35: C44.2@5140,2539.91 5170.69,2509.22 R52.2@5170.69,2467.96
NetC45_2: C45.2 R53.2 | length 87.2
  Bottom Layer w30: C45.2@4301.45,2460.83 4301.45,2374.92 R53.2@4302.37,2374
NetC50_1: C50.1 R48.1 R49.2 R50.2 U5.2 | length 433.4
  Bottom Layer w20: R50.2@5363,1767.01 U5.2@5423.85,1767.01 ; U5.2@5424.6,1767.76 5428.76,1767.76 5491.5,1830.5 C50.1@5561,1830.5 5592,1861.5 R49.2@5628.16,1861.5 5729.97,1861.5 R48.1@5750,1841.52
NetC53_1: C53.1 U7.3 | length 66.3
  Bottom Layer w20: U7.3@4274.72,2832.11 4274.72,2896.87 C53.1@4275.82,2897.97
NetC54_1: C54.1 U8.3 | length 66.3
  Bottom Layer w20: U8.3@5031.79,2833.36 5031.79,2898.12 C54.1@5032.89,2899.22
NetC58_1: C58.1 R58.2 U1.3 | length 137.9
  Bottom Layer w25: R58.2@2677.5,727 2677.9,727.4 C58.1@2742.5,727.4 2742.5,675.57 U1.3@2727.73,660.8
NetC59_1: C59.1 R59.2 U9.3 | length 139.5
  Bottom Layer w25: R59.2@2656,2817.5 C59.1@2656,2885.11 2706.35,2885.11 U9.3@2721.6,2869.87
NetD1_3: D1.3 L1.4 Q1.2 | length 1108.1
  Top Layer w70: Q1.2@2977,2754.07 2749.63,2526.7 L1.4@2749.63,2186.56 3040.46,1895.73 D1.3@3075.54,1895.73
NetD2_1: D2.1 R4.1 R15.2 | length 153
  Bottom Layer w30: R15.2@2922,3024.91 2922.4,3025.31 D2.1@2997,3025.31 3065.06,3025.31 R4.1@3072,3018.37
NetD2_2: D2.2 Q1.1 R4.2 R6.2 | length 268.4
  Bottom Layer w25: D2.2@2997,2938.69 D2.2@2997.94,2939.63 ; Q1.1@3070.17,2854.01 3130.1,2794.07 R6.2@3152,2794.07 ; R4.2@3070.17,2937.8 R4.2@3072,2939.63
  Bottom Layer w30: D2.2@2997.94,2939.63 R4.2@3072,2939.63 ; Q1.1@3070.17,2854.01 R4.2@3070.17,2937.8
NetD3_2: D3.2 D9.2 L5.4 | length 1028.4
  Top Layer w50: L5.4@342.36,3016.63 423.37,3016.63 810,2630 D3.2@1102,2630
  Bottom Layer w50: D3.2@1102,2630 1106,2634 D9.2@1208.99,2634
NetD3_3: D3.3 D10.2 L5.3 | length 1264.1
  Top Layer w50: L5.3@663.64,3016.63 1108.37,3016.63 1253,2872 1253,2581 D3.3@1102,2430
  Bottom Layer w50: D3.3@1102,2430 1110,2438 D10.2@1208.99,2438
NetD4_1: D4.1 Q4.1 R62.1 | length 227.1
  Bottom Layer w20: R62.1@5090,2266.19 5105.05,2281.24 Q4.1@5148.6,2281.24 5234,2195.84 D4.1@5234,2154.31
NetD5_3: D5.3 L6.4 Q12.2 | length 1253.2
  Top Layer w70: L6.4@2749.63,69.56 2749.63,205.63 Q12.2@2977,433 2977,438.01 2889,526.01 2889,928.33 D5.3@3075.54,1114.87
NetD6_1: D6.1 R16.2 R18.1 | length 171.2
  Bottom Layer w30: R16.2@2910,665.37 2937.94,693.31 D6.1@2988,693.31 2989.42,691.89 R18.1@3069,691.89
NetD6_2: D6.2 Q12.1 R18.2 R19.2 | length 267.9
  Bottom Layer w30: D6.2@2988,606.69 2994.45,613.15 R18.2@3069,613.15 3070.17,611.98 Q12.1@3070.17,532.93
  Bottom Layer w50: Q12.1@3070.17,532.93 3086.07,532.93 R19.2@3148,471
NetD7_1: D7.1 R38.1 | length 79
  Bottom Layer w20: R38.1@5344.5,433 D7.1@5344.47,512
NetD8_1: D8.1 R40.1 | length 84
  Bottom Layer w20: D8.1@5920.53,495 5920.53,411.62 R40.1@5920.98,411.17
NetD20_1: D20.1 R74.1 U13.4 | length 177.9
  Bottom Layer w20: D20.1@2303.42,2593.31 2309.11,2599 R74.1@2392.42,2599 2392.42,2545.54 U13.4@2369.02,2522.13
NetF1_1: F1.1 J3.1
NetL7_2: L7.2 T1.1
NetQ2_1: Q2.1 Q14.2 R40.2 R45.2 | length 370.6
  Bottom Layer w20: R40.2@5852,405.19 5852,278 5879.4,250.6 Q14.2@5895.24,250.6
  Bottom Layer w25: Q2.1@5719,482 5719,461.5 R45.2@5769,411.5 5857.66,411.5 R40.2@5857.98,411.17 R40.2@5852,405.19
NetQ3_1: Q3.1 Q13.2 R38.2 R44.2 | length 376.4
  Bottom Layer w20: R44.2@5072,402.5 5103.5,402.5 5119.36,386.64 5167.8,386.64 Q13.2@5214.4,433.24 5281.26,433.24 R38.2@5281.5,433
  Bottom Layer w30: Q3.1@4964,482 4992.5,482 R44.2@5072,402.5
NetQ5_1: Q5.1 R60.1 | length 86.5
  Bottom Layer w30: Q5.1@4856.7,2655.06 4856.7,2697.33 R60.1@4888,2728.63
NetQ6_1: Q6.1 R63.2 R64.2 | length 126.6
  Bottom Layer w20: R63.2@4044.02,251.65 4044.02,191.45 Q6.1@4043.76,191.19 4052.96,181.99 R64.2@4106,181.99
NetQ6_3: Q6.3 R56.1 U4.3 | length 330
  Bottom Layer w20: U4.3@3779.36,190.49 3779.36,233.28 3805.43,259.34 R56.1@3949.92,259.34 3949.92,154.44 Q6.3@3949.27,153.79
NetQ7_1: Q7.1 R61.2 | length 91.8
  Bottom Layer w35: Q7.1@4100.7,2654.06 4100.7,2696.67 R61.2@4135.51,2731.48
NetQ10_1: Q10.1 R5.1 R14.1 | length 334.3
  Bottom Layer w30: R5.1@2688.61,1497 2726.86,1458.76 Q10.1@2726.86,1412.76 2796.62,1343 2867.65,1343 2883.5,1327.16 R14.1@2883.5,1285
NetR1_2: R1.2 U6.3 | length 64.7
  Bottom Layer w30: U6.3@5804,1349 5822.5,1330.5 R1.2@5822.5,1292
NetR10_1: R10.1 R22.2 | length 83.8
  Bottom Layer w20: R22.2@4675,1549 R10.1@4758.83,1549
NetR10_2: R10.2 U2.1 | length 1508.9
  Top Layer w20: v1(4873,1495) 4873,1122 v1(5022,973)
  Bottom Layer w20: v1(4873,1495) R10.2@4873,1549 ; v1(5022,973) 5022,903 5171.16,753.84 5665.72,753.84 5726.72,814.85 U2.1@5736.17,814.85
NetR15_1: R15.1 U9.5 | length 66.2
  Bottom Layer w30: U9.5@2796.4,2978.13 2796.49,2978.13 R15.1@2843.26,3024.91
NetR16_1: R16.1 U1.5 | length 74.6
  Bottom Layer w20: U1.5@2836,586 U1.5@2836.24,585.76
  Bottom Layer w30: U1.5@2836,586 2909.37,586 R16.1@2910,586.63
NetR17_1: R17.1 R47.2 U6.1 | length 140.1
  Bottom Layer w25: R17.1@5877.26,1778.03 5877.44,1777.85 R47.2@5877.44,1714.03 5904,1687.47 U6.1@5904,1649
NetR20_1: R20.1 R27.2 | length 93
  Bottom Layer w30: R27.2@2191,2024.84 2195.75,2020.09 R20.1@2282,2020.09
NetR21_1: R21.1 R33.1 | length 106.8
  Bottom Layer w25: R21.1@1765,467.09 R33.1@1765,573.91
NetR21_2: R21.2 R23.1 | length 94.3
  Bottom Layer w30: R23.1@1671.09,352 1764.09,352 R21.2@1765,352.91
NetR22_1: R22.1 R31.2 | length 83.8
  Bottom Layer w20: R31.2@4477,1549 R22.1@4560.83,1549
NetR27_1: R27.1 R34.2 | length 125.8
  Bottom Layer w30: R34.2@2110.94,1899.04 2111,1899.1 R27.1@2111,2024.84
NetR28_2: R28.2 R77.1 | length 289
  Bottom Layer w25: R77.1@2173.91,2296.91 2174,2297 R28.2@2174,2585.91
NetR29_2: R29.2 R36.1 | length 86.8
  Bottom Layer w40: R36.1@4383.54,1366.54 R29.2@4470.37,1366.54
NetR36_2: R36.2 R43.1 | length 86.8
  Bottom Layer w40: R43.1@4182.54,1366.54 R36.2@4269.37,1366.54
NetR46_2: R46.2 R86.1 | length 116
  Bottom Layer w30: R46.2@2191,2115 R86.1@2307,2115
NetR51_1: R51.1 R55.2 U4.7 | length 267.2
  Bottom Layer w20: R51.1@3607,363.5 R55.2@3669,363.5 3677.5,363.5 3693,348 3811,348 3829.36,366.36 U4.7@3829.36,397.18
NetR66_2: R66.2 U14.3 | length 181.5
  Bottom Layer w15: R66.2@6168.2,2078.1 6147.13,2057.03 6147.13,1953.03 6163.57,1936.6 U14.3@6188,1936.6
NetR67_1: R67.1 R68.1 R72.2 U11.3 | length 304.7
  Bottom Layer w15: R72.2@5535,2063.09 5533.87,2061.96 R68.1@5533.87,1997.08 5646.08,1997.08 5676.47,2027.47 U11.3@5676.47,2042.63 5719.36,2042.63 R67.1@5737,2024.99
NetR67_2: R67.2 R73.1 U11.4 U12.2 | length 514
  Bottom Layer w20: U11.4@5676.47,1934.36 5709.36,1934.36 R67.2@5733,1958 ; R67.2@5743,1948 5808.03,1948 5957.5,1798.52 R73.1@5957.5,1714.03
  Bottom Layer w25: R73.1@5957.5,1714.03 5957.5,1701.5 U12.2@6010,1649
NetR69_2: R69.2 U11.1 | length 84.3
  Bottom Layer w20: R69.2@5601.5,2126.87 5601.67,2126.7 U11.1@5601.67,2042.63
NetR70_1: R70.1 U12.4 | length 77
  Bottom Layer w25: U12.4@6110,1349 6153.5,1305.5 R70.1@6153.5,1290
NetR71_1: R71.1 R73.2 U12.1 | length 139.9
  Bottom Layer w30: R73.2@6020.5,1714.03 R71.1@6085,1714 6085,1674 U12.1@6110,1649
NetR78_2: R78.2 U14.4 | length 183.6
  Bottom Layer w15: U14.4@6079.73,1936.6 6104.43,1936.6 6124.43,1956.6 6124.43,2056.09 R78.2@6102.41,2078.1
NetR86_2: R86.2 R87.1 | length 94.9
  Bottom Layer w30: R87.1@2387,2020.09 R86.2@2387,2115
NetR89_2: R89.2 U3.3 | length 116
  Bottom Layer w20: U3.3@1936.28,1646.7 1975.78,1646.7 2029.58,1700.5 R89.2@2030,1700.5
